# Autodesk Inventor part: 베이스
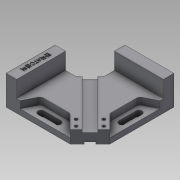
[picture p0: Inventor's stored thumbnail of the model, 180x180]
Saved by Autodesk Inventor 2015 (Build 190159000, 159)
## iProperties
Created: 2019-04
Part Number: 베이스
Material: 일반
Document SubType Name: Modeling
Designer: SCD-A02
Density: 1 g/cm^3
Appearance: 기본값
Author: SCD-A02
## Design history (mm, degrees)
sketch "스케치2"
  geometry: L1 (0, 0)-(120, 0); L2 (120, 0)-(120, 120); L3 (120, 120)-(0, 120); L4 (0, 120)-(0, 0)
  constraints: 8 end point, 2 parallel, 1 horizontal, 1 perpendicular
  dimensions: "d2" = 120 distance of L2.end L3.end; "d3" = 120 distance of L1.end L2.end
extrude "돌출1" new body sketch "스케치2" distance "d4" = 18; taper "d5" = 0 deg
sketch "스케치3"
  geometry: L1 (0, 0)-(120, 0) reference; L2 (0, 0)-(120, 0) reference; L3 (120, 0)-(120, 120) reference; L4 (120, 120)-(0, 120) reference; L5 (0, 120)-(0, 0) reference; L6 (120, 28.284)-(91.716, 0); L7 (120, 28.284)-(120, 0); L8 (91.716, 0)-(120, 0)
  constraints: 6 end point, 2 point on line, 1 collinear, 1 perpendicular
  dimensions: "d8" = 45 deg angle of L6 L1; "d9" = 40 distance of L6.start L6.end
extrude "돌출2" cut sketch "스케치3" stored distance "d10" = 8; taper "d11" = 0 deg
sketch "스케치4"
  geometry: L1 (120, 28.284)-(120, 120) reference; L2 (120, 120)-(0, 120) reference; L3 (0, 120)-(0, 0) reference; L4 (0, 0)-(91.716, 0) reference; L5 (0, 70)-(15, 70); L6 (15, 70)-(15, 0); L7 (0, 0)-(0, 70); L8 (0, 0)-(15, 0); L9 (50, 120)-(50, 105); L10 (50, 105)-(120, 105); L11 (120, 120)-(50, 120); L12 (120, 120)-(120, 105)
  constraints: 16 end point, 4 collinear, 4 point on line, 3 perpendicular, 1 horizontal
  dimensions: "d12" = 50 distance from line of L2.end L5; "d13" = 15 distance of L5.start L5.end; "d14" = 15 distance of L9.start L9.end; "d15" = 50 distance from line of L2.end L9
extrude "돌출3" join sketch "스케치4" distance "d16" = 24; taper "d17" = 0 deg
sketch "스케치6"
  geometry: L1 (15, 0)-(91.716, 0) reference; L2 (91.716, 0)-(120, 28.284) reference; L3 (120, 28.284)-(120, 105) reference; L4 (20, 0)-(30, 20); L5 (30, 20)-(71.716, 20); L6 (71.716, 20)-(91.716, 0); L7 (120, 28.284)-(100, 48.284); L8 (100, 48.284)-(100, 90); L9 (100, 90)-(120, 100); L10 (120, 120)-(0, 120) reference; L11 (120, 28.284)-(120, 120) reference; 1 further point
  constraints: 12 end point, 2 point on line, 1 horizontal, 1 vertical
  dimensions: "d19" = 20 distance of point (0, 0) L4.start; "d20" = 20 distance from line of L10 L9.end; "d21" = 30 horizontal distance of point (0, 0) L4.end; "d22" = 30 distance from line of L10 L8.end; "d23" = 20 distance between parallel lines of L1 L5; "d24" = 20 distance between parallel lines of L11 L8; "d25" = 90 deg angle of L2 L6; "d26" = 90 deg angle of L2 L7
extrude "돌출4" cut sketch "스케치6" distance "d27" = 10; taper "d28" = 0 deg
sketch "스케치7"
  geometry: L1 (91.716, 0)-(20, 0) reference; L2 (40, 10)-(64, 10); L3 (40, 5.5)-(64, 5.5); L4 (64, 14.5)-(40, 14.5); L5 (110, 56)-(110, 80); L6 (105.5, 56)-(105.5, 80); L7 (114.5, 80)-(114.5, 56); L8 (120, 100)-(120, 28.284) reference; L9 (100, 90)-(120, 100) reference; L10 (100, 48.284)-(100, 90) reference; L11 (120, 28.284)-(100, 48.284) reference; L12 (71.716, 20)-(91.716, 0) reference; L13 (30, 20)-(71.716, 20) reference; L14 (20, 0)-(30, 20) reference; L15 (91.716, 0)-(20, 0) reference; L16 (120, 120)-(50, 120) reference; A1 r 4.5 centre (40, 10) between (40, 14.5) and (40, 5.5); A2 r 4.5 centre (64, 10) between (64, 5.5) and (64, 14.5); A3 r 4.5 centre (110, 56) between (105.5, 56) and (114.5, 56); A4 r 4.5 centre (110, 80) between (114.5, 80) and (105.5, 80); 3 further points
  constraints: 16 end point, 8 point on circle, 8 tangent, 4 centre point, 2 midpoint, 2 parallel, 1 horizontal, 1 vertical
  dimensions: "d29" = 24 distance of L2.end L2.start; "d30" = 24 distance of L5.start L5.end; "d31" = 10 distance from line of L1 point (52, 10); "d32" = 10 distance from line of L8 point (110, 68); "d34" = 40 horizontal distance of point (0, 0) L2.start; "d35" = 40 distance from line of L16 L5.end; "d37" = 9 distance between parallel lines of L3 L4; "d38" = 9 distance between parallel lines of L7 L6
extrude "돌출5" cut sketch "스케치7" stored distance "d39" = 10; taper "d40" = 0 deg
sketch "스케치8"
  geometry: L1 (91.716, 0)-(120, 28.284) reference; L2 (50, 120)-(0, 120) reference; L3 (0, 0)-(15, 0) reference; L4 (15, 0)-(15, 70) reference; L5 (15, 70)-(0, 70) reference; L6 (0, 70)-(0, 0) reference; L7 (120, 120)-(50, 120) reference; L8 (50, 120)-(50, 105) reference; L9 (50, 105)-(120, 105) reference; L10 (120, 105)-(120, 120) reference; L11 (20, 0)-(30, 20) reference; L12 (30, 20)-(71.716, 20) reference; L13 (71.716, 20)-(91.716, 0) reference; L14 (91.716, 0)-(120, 28.284) reference; L15 (120, 28.284)-(100, 48.284) reference; L16 (100, 48.284)-(100, 90) reference; L17 (100, 90)-(120, 100) reference; L18 (120, 100)-(120, 105) reference; L19 (120, 105)-(50, 105) reference; L20 (50, 105)-(50, 120) reference; L21 (50, 120)-(0, 120) reference; L22 (0, 120)-(0, 70) reference; L23 (0, 70)-(15, 70) reference; L24 (15, 70)-(15, 0) reference; L25 (15, 0)-(20, 0) reference; L26 (15, 70)-(0, 70) reference; L27 (50, 120)-(50, 105) reference; L28 (0, 120)-(0, 70); L29 (0, 120)-(50, 120); L30 (105.858, 14.142)-(40.097, 79.903); L31 (111.515, 19.799)-(45.754, 85.56); L32 (100.201, 8.485)-(34.44, 74.246); L33 (30.194, 70)-(50, 89.806); L34 (0, 70)-(30.194, 70); L35 (50, 89.806)-(50, 120); L36 (100.201, 8.485)-(111.515, 19.799); 1 further point
  constraints: 18 end point, 3 parallel, 3 perpendicular, 2 collinear, 2 point on line, 1 horizontal, 1 midpoint
  dimensions: "d43" = 93 distance of L30.start L30.end; "d44" = 8 distance between parallel lines of L30 L31; "d45" = 8 distance between parallel lines of L30 L32; "d46" = 93 distance between parallel lines of L1 L33; "d49" = 93 distance between parallel lines of L33 L36
  node "투영된 루프4"
  node "투영된 루프5"
  node "투영된 루프6"
extrude "돌출6" cut sketch "스케치8" stored distance "d47" = 10; taper "d48" = 0 deg
extrude "돌출7" cut sketch "스케치8" distance "d50" = 3.5; taper "d51" = 0 deg
sketch "스케치9"
  geometry: L1 (-30.194, 70)-(-50, 89.806) reference; L2 (-120, 28.284)-(-91.716, 0) reference; L3 (-105.858, 14.142)-(-40.097, 79.903); L4 (-110.101, 18.385)-(-44.34, 84.146); L5 (-101.615, 9.899)-(-35.854, 75.66); L6 (-44.34, 84.146)-(-35.854, 75.66); L7 (-110.101, 18.385)-(-101.615, 9.899)
  constraints: 10 end point, 2 collinear, 2 midpoint, 2 parallel, 1 point on line
  dimensions: "d52" = 6 distance between parallel lines of L3 L4; "d53" = 6 distance between parallel lines of L3 L5; "d55" = 93 distance from line of L2 L5.end
extrude "돌출8" cut sketch "스케치9" distance "d56" = 3; taper "d57" = 0 deg
sketch "스케치10"
  geometry: L1 (15, 70)-(0, 70) reference; 1 further point
  constraints: 1 other
  dimensions: "d58" = 7.5 horizontal distance of point (7.5, 35) L1.end; "d59" = 35 distance from line of L1 point (7.5, 35)
feature "엠보싱1" sketch "스케치10" dims "d60" = 0.5, "d61" = 0
sketch "스케치11"
  geometry: L1 (100.201, 8.485)-(34.44, 74.246) reference; L2 (34.44, 74.246)-(30.194, 70) reference; L3 (30.194, 70)-(15, 70) reference; L4 (15, 70)-(15, 0) reference; L5 (15, 0)-(20, 0) reference; L6 (20, 0)-(30, 20) reference; L7 (30, 20)-(71.716, 20) reference; L8 (45.754, 85.56)-(111.515, 19.799) reference; L9 (111.515, 19.799)-(120, 28.284) reference; L10 (120, 28.284)-(100, 48.284) reference; L11 (100, 48.284)-(100, 90) reference; L12 (100, 90)-(120, 100) reference; L13 (120, 100)-(120, 105) reference; L14 (120, 105)-(50, 105) reference; L15 (50, 105)-(50, 89.806) reference; L16 (50, 89.806)-(45.754, 85.56) reference; L17 (91.716, 0)-(100.201, 8.485) reference; L18 (111.515, 19.799)-(100.201, 8.485) reference; L19 (105.858, 14.142)-(103.926, 16.074); L20 (0, 0)-(0, 6); L21 (71.716, 20)-(91.716, 0) reference; 4 further points
  constraints: 4 end point, 1 midpoint, 1 vertical
  dimensions: "d67" = 6 distance from line of L9 point (111.515, 28.284); "d68" = 6 distance from line of L17 point (91.716, 8.485); "d69" = 28 distance of point (111.515, 28.284) point (91.716, 8.485); "d72" = 1.93171 horizontal distance of L19.start L19.end; "d73" = 90 deg angle of L19 L18; "d75" = 6 distance of L20.start L20.end; "d76" = 6 distance from line of L21 point (91.716, 8.485); "d77" = 12 distance of point (83.23, 16.971) point (91.716, 8.485); "d78" = 6 distance from line of L21 point (83.23, 16.971); "d79" = 12 distance of point (103.029, 36.77) point (111.515, 28.284); "d80" = 6 distance from line of L8 point (103.029, 36.77)
  node "투영된 루프7"
sketch "스케치12"
  geometry: L1 (64, 14.5)-(40, 14.5) reference; L2 (40, 5.5)-(64, 5.5) reference; L3 (35.854, 75.66)-(101.615, 9.899) reference; L4 (101.615, 9.899)-(91.716, 0) reference; L5 (0, 0)-(91.716, 0) reference; L6 (0, 70)-(0, 0) reference; L7 (0, 70)-(30.194, 70) reference; L8 (30.194, 70)-(35.854, 75.66) reference; L9 (110.101, 18.385)-(44.34, 84.146) reference; L10 (44.34, 84.146)-(50, 89.806) reference; L11 (50, 89.806)-(50, 120) reference; L12 (120, 120)-(50, 120) reference; L13 (120, 28.284)-(120, 120) reference; L14 (120, 28.284)-(110.101, 18.385) reference; L15 (114.5, 56)-(114.5, 80) reference; L16 (105.5, 80)-(105.5, 56) reference; A1 r 4.5 centre (64, 10) between (64, 5.5) and (64, 14.5) reference; A2 r 4.5 centre (40, 10) between (40, 14.5) and (40, 5.5) reference; A3 r 4.5 centre (110, 56) between (105.5, 56) and (114.5, 56) reference; A4 r 4.5 centre (110, 80) between (114.5, 80) and (105.5, 80) reference; 9 further points
  constraints: 4 coincident
hole "구멍1" sketch "스케치12" at (83.23, 16.971), (91.716, 8.485), (111.515, 28.284), (103.029, 36.77) diameter "d81" = 4.5; stored, may be unused: countersink angle "d85" = 90 deg, drill point angle "d87" = 0 deg; dims "d82" = 6, "d83" = 8, "d84" = 10, "d86" = 18
fillet "모깎기1" dims "d88" = 5
node "솔리드1"
node "투영된 루프1"
node "투영된 루프2"
node "투영된 루프3"
node "투영된 루프8"
node "투영된 루프9"
